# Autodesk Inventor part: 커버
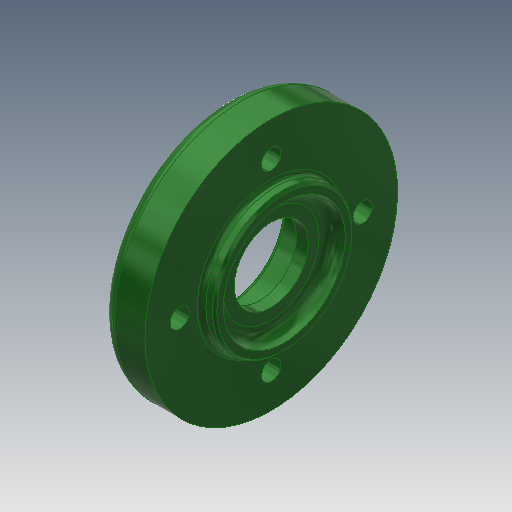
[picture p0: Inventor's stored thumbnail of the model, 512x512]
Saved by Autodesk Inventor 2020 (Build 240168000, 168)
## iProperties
Created: 2015-11
Part Number: 커버
Material: 알루미늄 6061
Document SubType Name: Modeling
Designer: mduedu
Density: 2.71 g/cm^3
Mass: 57.8273 g
Surface Area: 81.1807 cm^2
Volume: 21.3385 cm^3
Appearance: 매끄러움 - 짙은 산림 녹색
Author: mduedu
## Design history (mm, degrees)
sketch "스케치1"
  geometry: L1 (-6.5, 0)-(6.5, 0); L2 (-6.5, 0)-(-6.5, 29); L3 (-6.5, 29)-(3.5, 29); L4 (3.5, 29)-(3.5, 16); L5 (3.5, 16)-(6.5, 16); L6 (6.5, 16)-(6.5, 0); 2 further points
  constraints: 12 end point, 3 perpendicular, 2 parallel, 1 coincident, 1 horizontal, 1 midpoint
  dimensions: "d0" = 13 distance of L1.start L1.end; "d1" = 58 diameter of L3 L1; "d2" = 3 distance of L4.end L5.end; "d3" = 32 diameter of L5 L1
revolve "회전1" sketch "스케치1" stored, may be unused: angle "d4" = 90 deg
hole "구멍1" diameter "d7" = 28; stored, may be unused: countersink angle "d11" = 90 deg, drill point angle "d13" = 0 deg; dims "d8" = 6, "d9" = 4, "d10" = 2, "d12" = 3, "d65" = 10, "d66" = 10
hole "구멍2" diameter "d16" = 25; stored, may be unused: countersink angle "d20" = 90 deg, drill point angle "d22" = 0 deg; dims "d17" = 6, "d18" = 4, "d19" = 2, "d21" = 7.3, "d67" = 10, "d68" = 10
hole "구멍3" diameter "d25" = 17; stored, may be unused: countersink angle "d29" = 90 deg, drill point angle "d31" = 0 deg; dims "d23" = 10, "d24" = 10, "d26" = 6, "d27" = 4, "d28" = 2, "d30" = 4.2
chamfer "모따기1" distance "d32" = 0.7; stored, may be unused: second distance "d33" = 2, angle "d34" = 30 deg
fillet "모깎기1" dims "d35" = 0.2
fillet "모깎기2" dims "d36" = 3
fillet "모깎기3" dims "d37" = 3
fillet "모깎기4" dims "d38" = 1
sketch "스케치3" dims "d61" = 42
  geometry: C1 r 29 at (0, 0) reference; 2 further points
  constraints: 2 vertical alignment, 1 coincident, 2 other
hole "구멍4" sketch "스케치3" at (0, -21) diameter "d44" = 4.5; stored, may be unused: countersink angle "d48" = 90 deg, drill point angle "d50" = 0 deg; dims "d45" = 6, "d46" = 8, "d47" = 4.6, "d49" = 8
chamfer "모따기2" distance "d62" = 0.5; stored, may be unused: second distance "d63" = 2, angle "d64" = 45 deg
node "솔리드1"
pattern_circular "원형 패턴1" dims angle "d54" = 360 deg
